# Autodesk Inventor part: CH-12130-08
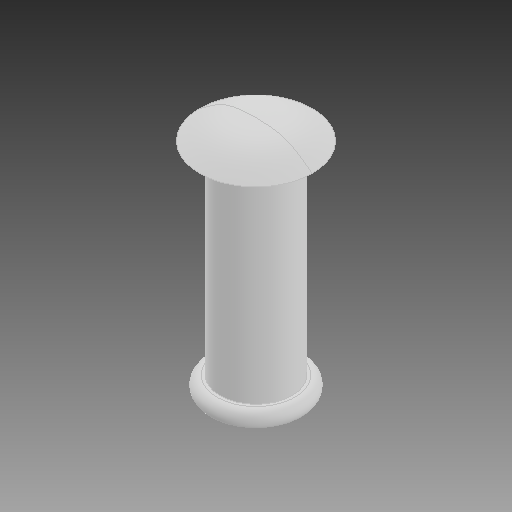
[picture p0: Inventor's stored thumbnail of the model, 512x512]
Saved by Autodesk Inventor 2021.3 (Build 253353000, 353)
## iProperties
Created: 2020-03
Part Number: CH-12130-08
Material: Ogólny
Document SubType Name: Modeling
Designer: Przemyslaw Krecisz
Density: 1 g/cm^3
Appearance: Domyślna
Author: Przemyslaw Krecisz
Revision Number: ÈÎºÎ
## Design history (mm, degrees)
feature "Ô²½Ç2"
node "Bryła1"
